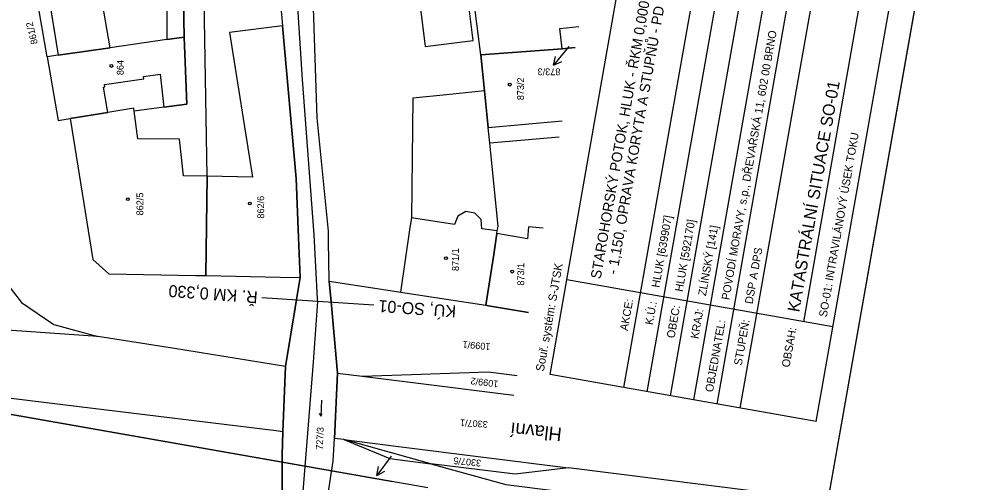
# Model space of a CAD drawing. Extents: x -534481 to -534262, y -1190577 to -1190138.
# Drawn here: x -534379.7 to -534261.7, y -1190257.6 to -1190199.6 of the extents above; entities that cross this region are included whole.
import ezdxf

# ---------------------------------------------------------------- set-up
doc = ezdxf.new("R2010")
doc.units = 0
for name, color, linetype in [('_KN_Povodí_Moravy', 7, 'Continuous'), ('_N_osa', 7, 'Continuous'), ('_N_tenká', 7, 'Continuous'), ('_N_text', 7, 'Continuous'), ('_rozpiska', 7, 'Continuous'), ('_rámeček', 7, 'Continuous'), ('_rámeček_mřížka', 7, 'Continuous'), ('_tenka', 7, 'Continuous'), ('Hranice parcel', 7, 'Continuous'), ('Parcelní čísla', 7, 'Continuous'), ('Polygon budovy', 7, 'Continuous'), ('Pop  PČ popisy', 7, 'Continuous'), ('Značky budov', 7, 'Continuous')]:
    doc.layers.add(name, color=color, linetype=linetype)

msp = doc.modelspace()

# ---------------------------------------------------------------- linework, layer by layer
at = {"layer": '_KN_Povodí_Moravy'}
for p, q in [((-534344.81, -1190226.96), (-534344.61, -1190231.96)), ((-534346.43, -1190243.1), (-534346.75, -1190251.25)), ((-534340.33, -1190252.09), (-534339.93, -1190243.93))]:
    msp.add_line(p, q, dxfattribs=at)
for points in [[(-534340.96, -1190232.41), (-534341.05, -1190227.37), (-534341.07, -1190226.16), (-534342.47, -1190212), (-534343.03, -1190195.73), (-534343.24, -1190185.5)], [(-534347.19, -1190196.18), (-534346.8, -1190200.49), (-534345.1, -1190219.6), (-534344.81, -1190226.96)], [(-534344.61, -1190231.96), (-534345.06, -1190234.73), (-534345.23, -1190235.77), (-534346.43, -1190243.1)], [(-534339.93, -1190243.93), (-534340.69, -1190235.47), (-534340.96, -1190232.41)], [(-534346.75, -1190251.25), (-534346.86, -1190254.17), (-534346.83, -1190264.15), (-534347.63, -1190264.06)], [(-534341.18, -1190264.8), (-534341.99, -1190264.71), (-534340.47, -1190254.93), (-534340.33, -1190252.09)]]:
    msp.add_lwpolyline(points, dxfattribs=at)
at = {"layer": '_N_osa'}
for points in [[(-534342.43, -1190234.65), (-534342.86, -1190226.62), (-534344.32, -1190207.2), (-534345.26, -1190192.29), (-534345.89, -1190175.46), (-534346.05, -1190156.96), (-534344.26, -1190151.93), (-534342.46, -1190149.21)], [(-534342.94, -1190242.55), (-534342.94, -1190242.55), (-534342.41, -1190234.98), (-534342.43, -1190234.65)], [(-534344.68, -1190264.49), (-534342.94, -1190242.55)]]:
    msp.add_lwpolyline(points, dxfattribs=at)
at = {"layer": '_N_tenká'}
msp.add_line((-534335.42, -1190235.41), (-534349.39, -1190234.5), dxfattribs=at)
at = {"layer": '_rozpiska'}
for p, q in [((-534313.39, -1190244.11), (-534298.63, -1190160.4)), ((-534304.17, -1190245.74), (-534289.41, -1190162.03)), ((-534301.26, -1190246.25), (-534286.5, -1190162.54)), ((-534298.35, -1190246.76), (-534283.59, -1190163.05)), ((-534295.44, -1190247.28), (-534280.68, -1190163.57)), ((-534292.53, -1190247.79), (-534277.77, -1190164.08)), ((-534280.15, -1190249.97), (-534265.39, -1190166.26)), ((-534289.62, -1190248.3), (-534276.27, -1190172.64)), ((-534281.7, -1190237.49), (-534270.45, -1190173.67)), ((-534278.06, -1190238.13), (-534311.31, -1190232.27)), ((-534280.15, -1190249.97), (-534313.39, -1190244.11))]:
    msp.add_line(p, q, dxfattribs=at)
at = {"layer": '_rámeček'}
msp.add_line((-534279.9, -1190266.87), (-534261.67, -1190163.46), dxfattribs=at)
for points in [[(-534407.91, -1190137.67), (-534480.84, -1190551.29), (-534334.6, -1190577.08), (-534261.67, -1190163.46)], [(-534261.67, -1190163.46), (-534407.91, -1190137.67), (-534426.15, -1190241.08), (-534333.07, -1190257.49)], [(-534328.65, -1190258.27), (-534426.15, -1190241.08), (-534444.38, -1190344.48), (-534298.13, -1190370.27)]]:
    msp.add_lwpolyline(points, dxfattribs=at)
at = {"layer": '_rámeček_mřížka'}
msp.add_lwpolyline([(-534480.84, -1190551.29), (-534334.6, -1190577.08), (-534261.67, -1190163.46)], dxfattribs=at)
at = {"layer": '_tenka'}
for p, q in [((-534341.95, -1190247.3), (-534342.04, -1190249.3)), ((-534342.04, -1190249.3), (-534342.2, -1190248.97)), ((-534342.04, -1190249.3), (-534341.86, -1190248.98))]:
    msp.add_line(p, q, dxfattribs=at)
at = {"layer": 'Hranice parcel'}
for p, q in [((-534322.05, -1190204.13), (-534324.69, -1190183.16)), ((-534376.21, -1190204.38), (-534377.99, -1190194.05)), ((-534376.48, -1190193.87), (-534374.83, -1190204.15)), ((-534359.16, -1190197.55), (-534359.11, -1190201.91)), ((-534322.05, -1190204.13), (-534311.89, -1190203.37)), ((-534311.89, -1190203.37), (-534310.25, -1190203.21)), ((-534374.83, -1190204.15), (-534376.21, -1190204.38)), ((-534321.59, -1190208.63), (-534322.05, -1190204.13)), ((-534312.23, -1190214.42), (-534320.92, -1190215.18)), ((-534332.08, -1190233.8), (-534321.41, -1190235.44)), ((-534369.86, -1190239.33), (-534400.65, -1190237.26)), ((-534346.75, -1190251.25), (-534346.43, -1190243.1)), ((-534339.93, -1190243.93), (-534340.33, -1190252.09)), ((-534339.93, -1190243.93), (-534336.87, -1190244.31)), ((-534336.87, -1190244.31), (-534330.88, -1190245.06)), ((-534330.88, -1190245.06), (-534317.91, -1190246.67)), ((-534339.16, -1190252.24), (-534340.33, -1190252.09)), ((-534328.28, -1190255.25), (-534339.16, -1190252.24)), ((-534339.16, -1190252.24), (-534332.3, -1190253.1)), ((-534332.3, -1190253.1), (-534311.1, -1190255.76))]:
    msp.add_line(p, q, dxfattribs=at)
for points in [[(-534340.96, -1190232.41), (-534341.05, -1190227.37), (-534341.07, -1190226.16), (-534342.47, -1190212), (-534343.03, -1190195.73), (-534343.24, -1190185.5)], [(-534393.17, -1190187.48), (-534393.12, -1190187.67), (-534387.8, -1190211.29), (-534384.29, -1190226.41), (-534381.99, -1190231.76), (-534379.42, -1190235.11), (-534375.39, -1190237.83), (-534369.86, -1190239.33)], [(-534347.19, -1190196.18), (-534346.8, -1190200.49), (-534345.1, -1190219.6), (-534344.81, -1190226.96), (-534344.61, -1190231.96)], [(-534356.39, -1190231.73), (-534356.2, -1190219.31), (-534356.58, -1190197.27)], [(-534311.89, -1190203.37), (-534312.15, -1190200.81), (-534309.78, -1190200.56)], [(-534359.11, -1190201.91), (-534361.27, -1190202.22), (-534368.34, -1190203.23), (-534374.83, -1190204.15)], [(-534359.11, -1190201.91), (-534358.74, -1190210.28), (-534361.62, -1190210.66), (-534365.33, -1190211.15), (-534365.38, -1190210.8), (-534368.64, -1190211.34), (-534373.35, -1190212.08)], [(-534376.21, -1190204.38), (-534374.83, -1190212.32), (-534373.35, -1190212.08)], [(-534321.59, -1190208.63), (-534326.31, -1190209.11), (-534330.53, -1190209.55), (-534330.71, -1190224.5), (-534330.89, -1190225.71), (-534332.08, -1190233.8)], [(-534320.92, -1190215.18), (-534321.12, -1190213.19), (-534321.59, -1190208.63)], [(-534373.35, -1190212.08), (-534370.52, -1190229.73), (-534368.51, -1190231.49), (-534357.69, -1190231.7), (-534356.39, -1190231.73)], [(-534321.41, -1190235.44), (-534320.43, -1190229.08), (-534320.03, -1190226.45), (-534319.98, -1190226.15), (-534319.89, -1190225.56), (-534320.92, -1190215.18)], [(-534356.39, -1190231.73), (-534347.08, -1190231.91), (-534344.61, -1190231.96)], [(-534346.43, -1190243.1), (-534345.23, -1190235.77), (-534345.06, -1190234.73), (-534344.61, -1190231.96)], [(-534340.96, -1190232.41), (-534340.69, -1190235.47), (-534339.93, -1190243.93)], [(-534340.96, -1190232.41), (-534332.26, -1190233.77), (-534332.08, -1190233.8)], [(-534316.09, -1190236.35), (-534321.08, -1190235.49), (-534321.41, -1190235.44)], [(-534360.3, -1190240.86), (-534369.86, -1190239.33)], [(-534346.43, -1190243.1), (-534360.3, -1190240.86)], [(-534330.71, -1190244.1), (-534321.13, -1190243.77), (-534317.48, -1190244.22)], [(-534336.87, -1190244.31), (-534330.71, -1190244.1)], [(-534372.22, -1190248.14), (-534389.59, -1190246.03), (-534397.44, -1190245.57), (-534405.02, -1190245.73), (-534413.23, -1190246.52)], [(-534346.75, -1190251.25), (-534347.61, -1190251.14), (-534372.22, -1190248.14)], [(-534347.63, -1190264.06), (-534346.83, -1190264.15), (-534346.86, -1190254.17), (-534346.75, -1190251.25)], [(-534341.18, -1190264.8), (-534341.99, -1190264.71), (-534340.47, -1190254.93), (-534340.33, -1190252.09)], [(-534339.16, -1190252.24), (-534333.42, -1190254.61), (-534328.28, -1190255.25)], [(-534311.1, -1190255.76), (-534317.76, -1190256.55), (-534328.28, -1190255.25)], [(-534328.28, -1190255.25), (-534318.9, -1190257.84), (-534317.93, -1190257.96), (-534281.65, -1190262.55), (-534282.51, -1190261.06), (-534283.8, -1190259.83), (-534285.39, -1190259.03)], [(-534285.39, -1190259.03), (-534287.93, -1190258.69), (-534311.1, -1190255.76)]]:
    msp.add_lwpolyline(points, dxfattribs=at)
at = {"layer": 'Polygon budovy'}
for points in [[(-534325.28, -1190183.96), (-534342.24, -1190186.06), (-534341.16, -1190195.04), (-534330.16, -1190193.66), (-534328.97, -1190203.08), (-534323, -1190202.33)], [(-534359.17, -1190196.28), (-534359.52, -1190191.38), (-534362.41, -1190191.8), (-534370.79, -1190193.02), (-534376.48, -1190193.87), (-534374.83, -1190204.15), (-534368.34, -1190203.23), (-534369.28, -1190197.69), (-534361.25, -1190196.57), (-534361.27, -1190202.22), (-534359.11, -1190201.91), (-534359.16, -1190197.55)], [(-534356.39, -1190231.73), (-534347.08, -1190231.91), (-534344.61, -1190231.96), (-534344.81, -1190226.96), (-534345.1, -1190219.6), (-534346.8, -1190200.49), (-534353.41, -1190201.32), (-534350.57, -1190219.42), (-534356.2, -1190219.31)], [(-534374.83, -1190204.15), (-534376.21, -1190204.38), (-534374.83, -1190212.32), (-534373.35, -1190212.08), (-534368.64, -1190211.34), (-534369.15, -1190208.17), (-534369.02, -1190208.12), (-534369.05, -1190207.85), (-534364.11, -1190207.12), (-534364.16, -1190206.82), (-534362.08, -1190206.54), (-534361.62, -1190210.66), (-534358.74, -1190210.28), (-534359.11, -1190201.91), (-534361.27, -1190202.22), (-534368.34, -1190203.23)], [(-534370.52, -1190229.73), (-534368.51, -1190231.49), (-534357.69, -1190231.7), (-534356.39, -1190231.73), (-534356.2, -1190219.31), (-534359.16, -1190219.26), (-534359.68, -1190214.65), (-534364.87, -1190214.64), (-534365.33, -1190211.15), (-534365.38, -1190210.8), (-534368.64, -1190211.34), (-534373.35, -1190212.08)], [(-534330.71, -1190224.5), (-534330.89, -1190225.71), (-534332.08, -1190233.8), (-534321.41, -1190235.44), (-534320.43, -1190229.08), (-534320.03, -1190226.45), (-534319.98, -1190226.15), (-534321.92, -1190225.86), (-534322.01, -1190224.73), (-534322.78, -1190223.9), (-534323.9, -1190223.72), (-534324.89, -1190224.28), (-534325.32, -1190225.33)]]:
    msp.add_lwpolyline(points, close=True, dxfattribs=at)
for points in [[(-534310.25, -1190203.21), (-534311.89, -1190203.37), (-534322.05, -1190204.13), (-534321.59, -1190208.63), (-534321.12, -1190213.19), (-534311.87, -1190212.38)], [(-534314.23, -1190225.79), (-534316.08, -1190225.63), (-534316.21, -1190227.12), (-534320.03, -1190226.45), (-534320.43, -1190229.08), (-534321.41, -1190235.44), (-534321.08, -1190235.49), (-534316.09, -1190236.35)]]:
    msp.add_lwpolyline(points, dxfattribs=at)
at = {"layer": 'Pop  PČ popisy'}
for p, q in [((-534311.05, -1190203.08), (-534312.94, -1190205.41)), ((-534312.94, -1190205.41), (-534312.7, -1190204.31)), ((-534312.94, -1190205.41), (-534311.92, -1190204.94)), ((-534333.25, -1190254.29), (-534335.02, -1190256.72)), ((-534335.02, -1190256.72), (-534334.83, -1190255.61)), ((-534335.02, -1190256.72), (-534334.02, -1190256.2))]:
    msp.add_line(p, q, dxfattribs=at)
at = {"layer": 'Značky budov'}
for centre in [(-534368.19, -1190205.51), (-534318.43, -1190207.85), (-534366.14, -1190222.16), (-534350.88, -1190222.72), (-534326.39, -1190229.54), (-534318.12, -1190231.23)]:
    msp.add_circle(centre, 0.175, dxfattribs=at)

# ---------------------------------------------------------------- texts
at = {"layer": '_N_text'}
for s, p in [('Ř. KM 0,330', (-534349.86, -1190233.7)), ('KÚ, SO-01', (-534325.08, -1190235.48))]:
    msp.add_text(s, height=1.5, rotation=175.8322, dxfattribs=at).set_placement(p)
at = {"layer": '_rozpiska'}
for s, height, rotation, p in [('STAROHORSKÝ POTOK, HLUK - ŘKM 0,000 ', 1.2825, 80, (-534307.07, -1190232.21)), ('- 1,150, OPRAVA KORYTA A STUPŇŮ - PD', 1.2825, 80, (-534305.01, -1190231.64)), ('POVODÍ MORAVY, s.p., DŘEVAŘSKÁ 11, 602 00 BRNO', 1, 80, (-534291, -1190234.83)), ('KATASTRÁLNÍ SITUACE SO-01', 1.5, 80, (-534282.27, -1190236.37)), ('SO-01: INTRAVILÁNOVÝ ÚSEK TOKU', 1, 80.1038, (-534278.83, -1190236.98)), ('HLUK [639907]', 1, 80, (-534299.74, -1190233.29)), ('HLUK [592170]', 1, 80, (-534296.83, -1190233.8)), ('ZLÍNSKÝ [141]', 1, 80, (-534293.92, -1190234.32)), ('DSP A DPS', 1, 80, (-534288.09, -1190235.34)), ('Souř. systém: S-JTSK', 1.0419, 80, (-534314.17, -1190243.77)), ('AKCE:', 1, 80, (-534303.69, -1190238.68)), ('K.Ú.:', 1, 80, (-534300.56, -1190237.95)), ('OBEC:', 1, 80, (-534297.85, -1190239.61)), ('KRAJ:', 1, 80, (-534294.86, -1190239.69)), ('OBJEDNATEL:', 1, 80, (-534293.04, -1190246.36)), ('STUPEŇ:', 1, 80, (-534289.45, -1190243.02)), ('OBSAH:', 1, 80, (-534283.48, -1190243.26))]:
    msp.add_text(s, height=height, rotation=rotation, dxfattribs=at).set_placement(p)
at = {"layer": '_tenka'}
msp.add_text('727/3', height=0.85, rotation=87.4337, dxfattribs=at).set_placement((-534341.78, -1190253.53))
at = {"layer": 'Parcelní čísla'}
for s, rotation, p in [('861/2', 104, (-534377.36, -1190202.69)), ('864', 90, (-534366.65, -1190206.66)), ('873/3', 180, (-534312.1, -1190205.82)), ('873/2', 90, (-534316.65, -1190209.79)), ('862/5', 90, (-534364.2, -1190224.2)), ('862/6', 90, (-534349.1, -1190224.6)), ('871/1', 90, (-534324.78, -1190231.16)), ('873/1', 90, (-534316.62, -1190232.98)), ('1099/1', 175, (-534320.8, -1190240.21)), ('1099/2', 173, (-534319.8, -1190244.89)), ('3307/1', 176, (-534321.14, -1190249.93)), ('3307/5', 174.3362, (-534321.96, -1190254.78))]:
    msp.add_text(s, height=0.85, rotation=rotation, dxfattribs=at).set_placement(p)
at = {"layer": 'Pop  PČ popisy'}
msp.add_text('Hlavní', height=1.7, rotation=173.7878, dxfattribs=at).set_placement((-534311.85, -1190250.77))

doc.saveas('drawing.dxf')
